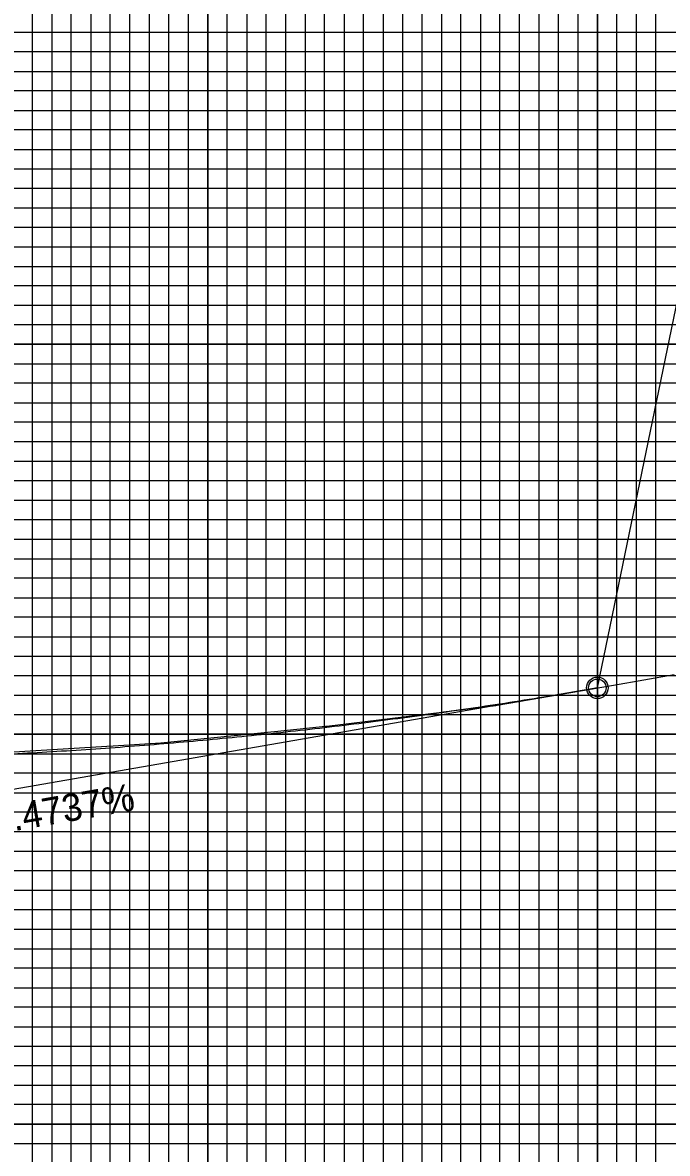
# Model space of a CAD drawing. Extents: x 573624 to 575507, y -53727 to -52273.
# Drawn here: x 574643.3 to 574808.8, y -52980.6 to -52690.6 of the extents above; entities that cross this region are included whole.
import ezdxf

# ---------------------------------------------------------------- set-up
doc = ezdxf.new("R2010")
doc.units = 0
for name, color, linetype in [('Exist Vertical Profile Ground Line', 7, 'Continuous'), ('Prop Vertical Profile Curve Label', 7, 'Continuous'), ('Prop Vertical Profile Grade', 7, 'Continuous'), ('Prop Vertical Profile Grade Label', 7, 'Continuous'), ('Prop VPI Label', 7, 'Continuous'), ('Sheet DOT Grid CELL', 7, 'Continuous'), ('Sheet Profile Grid Major CELL', 7, 'Continuous'), ('Sheet Profile Grid Middle CELL', 7, 'Continuous'), ('Sheet Profile Grid Minor CELL', 7, 'Continuous')]:
    doc.layers.add(name, color=color, linetype=linetype)

msp = doc.modelspace()

# ---------------------------------------------------------------- linework, layer by layer
at = {"layer": 'Exist Vertical Profile Ground Line'}
for p, q in [((574794.9, -52860.47), (574810.5, -52857.76)), ((574765.1, -52865.65), (574794.9, -52860.47)), ((574751.32, -52867.35), (574764.74, -52865.71)), ((574764.74, -52865.71), (574765.1, -52865.65)), ((574721.33, -52871.01), (574750.86, -52867.4)), ((574750.86, -52867.4), (574751.32, -52867.35)), ((574677.93, -52875.37), (574706.96, -52872.45)), ((574706.96, -52872.45), (574707.92, -52872.36)), ((574707.92, -52872.36), (574721.03, -52871.04)), ((574721.03, -52871.04), (574721.33, -52871.01)), ((574666.5, -52876.05), (574677.35, -52875.4)), ((574677.35, -52875.4), (574677.93, -52875.37)), ((574636.5, -52877.84), (574664.91, -52876.14)), ((574664.91, -52876.14), (574666.5, -52876.05))]:
    msp.add_line(p, q, dxfattribs=at)
at = {"layer": 'Prop Vertical Profile Curve Label'}
msp.add_circle((574790.78, -52861.19), 2.25, dxfattribs=at)
at = {"layer": 'Prop Vertical Profile Grade'}
msp.add_spline([(574290.78, -52846.49), (574300.78, -52848.78), (574310.78, -52850.98), (574320.78, -52853.1), (574330.78, -52855.14), (574340.78, -52857.1), (574350.78, -52858.98), (574360.78, -52860.78), (574370.78, -52862.49), (574380.78, -52864.13), (574390.78, -52865.68), (574400.78, -52867.15), (574410.78, -52868.54), (574420.78, -52869.85), (574430.78, -52871.08), (574440.78, -52872.22), (574450.78, -52873.29), (574460.78, -52874.27), (574470.78, -52875.18), (574480.78, -52876), (574490.78, -52876.74), (574500.78, -52877.4), (574510.78, -52877.98), (574520.78, -52878.47), (574530.78, -52878.89), (574540.78, -52879.22), (574550.78, -52879.48), (574560.78, -52879.65), (574570.78, -52879.74), (574580.78, -52879.75), (574590.78, -52879.68), (574600.78, -52879.52), (574610.78, -52879.29), (574620.78, -52878.98), (574630.78, -52878.58), (574640.78, -52878.1), (574650.78, -52877.54), (574660.78, -52876.9), (574670.78, -52876.18), (574680.78, -52875.38), (574690.78, -52874.49), (574700.78, -52873.53), (574710.78, -52872.48), (574720.78, -52871.35), (574730.78, -52870.14), (574740.78, -52868.85), (574750.78, -52867.48), (574760.78, -52866.03), (574770.78, -52864.5), (574780.78, -52862.88), (574790.78, -52861.19)], degree=3, dxfattribs=at)
at = {"layer": 'Prop VPI Label'}
for q in [(574820.41, -52717.75), (574543.48, -52904.14)]:
    msp.add_line((574790.78, -52861.19), q, dxfattribs=at)
msp.add_circle((574790.78, -52861.19), 2.75, dxfattribs=at)
at = {"layer": 'Sheet DOT Grid CELL'}
for p, q in [((574690.78, -52298.09), (574690.78, -53323.09)), ((574740.78, -52298.09), (574740.78, -53323.09)), ((574790.78, -52298.09), (574790.78, -53323.09)), ((573790.78, -52723.09), (575290.78, -52723.09)), ((573790.78, -52773.09), (575290.78, -52773.09)), ((573790.78, -52823.09), (575290.78, -52823.09)), ((573790.78, -52873.09), (575290.78, -52873.09)), ((573790.78, -52923.09), (575290.78, -52923.09)), ((573790.78, -52973.09), (575290.78, -52973.09))]:
    msp.add_line(p, q, dxfattribs=at)
at = {"layer": 'Sheet Profile Grid Major CELL'}
for points in [[(574690.78, -53323.09), (574690.78, -52298.09), (574740.78, -52298.09), (574740.78, -53323.09)], [(574790.78, -53323.09), (574790.78, -52298.09), (574840.78, -52298.09)], [(575290.78, -52773.09), (573790.78, -52773.09), (573790.78, -52723.09), (575290.78, -52723.09)], [(575290.78, -52873.09), (573790.78, -52873.09), (573790.78, -52823.09), (575290.78, -52823.09)], [(575290.78, -52973.09), (573790.78, -52973.09), (573790.78, -52923.09), (575290.78, -52923.09)]]:
    msp.add_lwpolyline(points, dxfattribs=at)
at = {"layer": 'Sheet Profile Grid Middle CELL'}
for points in [[(574665.78, -53323.09), (574665.78, -52298.09), (574715.78, -52298.09), (574715.78, -53323.09)], [(574765.78, -53323.09), (574765.78, -52298.09), (574815.78, -52298.09)], [(575290.78, -52698.09), (573790.78, -52698.09), (573790.78, -52748.09), (575290.78, -52748.09)], [(575290.78, -52798.09), (573790.78, -52798.09), (573790.78, -52848.09), (575290.78, -52848.09)], [(575290.78, -52898.09), (573790.78, -52898.09), (573790.78, -52948.09), (575290.78, -52948.09)]]:
    msp.add_lwpolyline(points, dxfattribs=at)
at = {"layer": 'Sheet Profile Grid Minor CELL'}
for points in [[(574645.78, -53323.09), (574645.78, -52298.09), (574650.78, -52298.09), (574650.78, -53323.09)], [(574655.78, -53323.09), (574655.78, -52298.09), (574660.78, -52298.09), (574660.78, -53323.09)], [(574670.78, -53323.09), (574670.78, -52298.09), (574675.78, -52298.09), (574675.78, -53323.09)], [(574680.78, -53323.09), (574680.78, -52298.09), (574685.78, -52298.09), (574685.78, -53323.09)], [(574695.78, -53323.09), (574695.78, -52298.09), (574700.78, -52298.09), (574700.78, -53323.09)], [(574705.78, -53323.09), (574705.78, -52298.09), (574710.78, -52298.09), (574710.78, -53323.09)], [(574720.78, -53323.09), (574720.78, -52298.09), (574725.78, -52298.09), (574725.78, -53323.09)], [(574730.78, -53323.09), (574730.78, -52298.09), (574735.78, -52298.09), (574735.78, -53323.09)], [(574745.78, -53323.09), (574745.78, -52298.09), (574750.78, -52298.09), (574750.78, -53323.09)], [(574755.78, -53323.09), (574755.78, -52298.09), (574760.78, -52298.09), (574760.78, -53323.09)], [(574770.78, -53323.09), (574770.78, -52298.09), (574775.78, -52298.09), (574775.78, -53323.09)], [(574780.78, -53323.09), (574780.78, -52298.09), (574785.78, -52298.09), (574785.78, -53323.09)], [(574795.78, -53323.09), (574795.78, -52298.09), (574800.78, -52298.09), (574800.78, -53323.09)], [(574805.78, -53323.09), (574805.78, -52298.09), (574810.78, -52298.09)], [(575240.78, -52693.09), (573840.78, -52693.09), (573840.78, -52703.09), (575240.78, -52703.09)], [(575240.78, -52708.09), (573840.78, -52708.09), (573840.78, -52713.09), (575240.78, -52713.09)], [(575240.78, -52718.09), (573840.78, -52718.09), (573840.78, -52728.09), (575240.78, -52728.09)], [(575240.78, -52733.09), (573840.78, -52733.09), (573840.78, -52738.09), (575240.78, -52738.09)], [(575240.78, -52743.09), (573840.78, -52743.09), (573840.78, -52753.09), (575240.78, -52753.09)], [(575240.78, -52758.09), (573840.78, -52758.09), (573840.78, -52763.09), (575240.78, -52763.09)], [(575240.78, -52768.09), (573840.78, -52768.09), (573840.78, -52778.09), (575240.78, -52778.09)], [(575240.78, -52783.09), (573840.78, -52783.09), (573840.78, -52788.09), (575240.78, -52788.09)], [(575240.78, -52793.09), (573840.78, -52793.09), (573840.78, -52803.09), (575240.78, -52803.09)], [(575240.78, -52808.09), (573840.78, -52808.09), (573840.78, -52813.09), (575240.78, -52813.09)], [(575240.78, -52818.09), (573840.78, -52818.09)], [(573840.78, -52828.09), (575240.78, -52828.09)], [(575240.78, -52833.09), (573840.78, -52833.09), (573840.78, -52838.09), (575240.78, -52838.09)], [(575240.78, -52843.09), (573840.78, -52843.09), (573840.78, -52853.09), (575240.78, -52853.09)], [(575240.78, -52858.09), (573840.78, -52858.09), (573840.78, -52863.09), (575240.78, -52863.09)], [(575240.78, -52868.09), (573840.78, -52868.09), (573840.78, -52878.09), (575240.78, -52878.09)], [(575240.78, -52883.09), (573840.78, -52883.09), (573840.78, -52888.09), (575240.78, -52888.09)], [(575240.78, -52893.09), (573840.78, -52893.09), (573840.78, -52903.09), (575240.78, -52903.09)], [(575240.78, -52908.09), (573840.78, -52908.09), (573840.78, -52913.09), (575240.78, -52913.09)], [(575240.78, -52918.09), (573840.78, -52918.09), (573840.78, -52928.09), (575240.78, -52928.09)], [(575240.78, -52933.09), (573840.78, -52933.09), (573840.78, -52938.09), (575240.78, -52938.09)], [(575240.78, -52943.09), (573840.78, -52943.09), (573840.78, -52953.09), (575240.78, -52953.09)], [(575240.78, -52958.09), (573840.78, -52958.09), (573840.78, -52963.09), (575240.78, -52963.09)], [(575240.78, -52968.09), (573840.78, -52968.09), (573840.78, -52978.09), (575240.78, -52978.09)]]:
    msp.add_lwpolyline(points, dxfattribs=at)

# ---------------------------------------------------------------- texts
at = {"layer": 'Prop Vertical Profile Grade Label'}
msp.add_text('(+)3.4737%', height=7, rotation=9.8532, dxfattribs=at).set_placement((574624.5, -52900.83))

doc.saveas('drawing.dxf')
